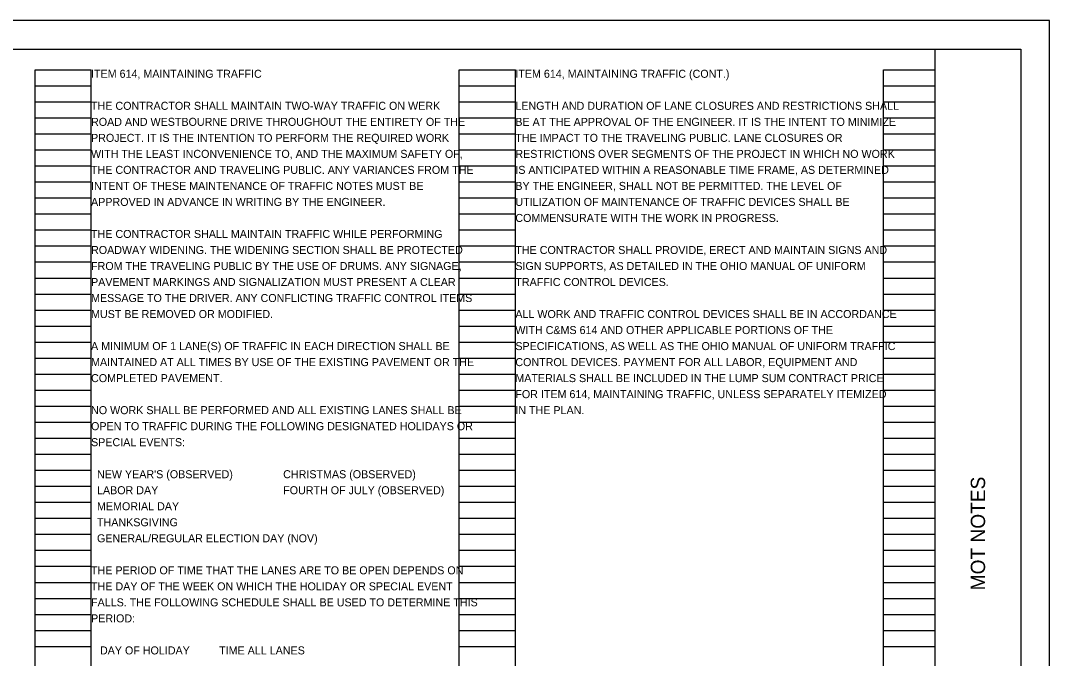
# Model space of a CAD drawing. Extents: x -8.1 to 34, y 0 to 22.
# Drawn here: x 16.01 to 34, y 10.85 to 22 of the extents above; entities that cross this region are included whole.
import ezdxf

# ---------------------------------------------------------------- set-up
doc = ezdxf.new("R2010")
doc.units = 0
for name, color, linetype in [('SH_Border', 7, 'Continuous'), ('SH_Cut_Line', 7, 'Continuous'), ('SH_Data', 7, 'Continuous'), ('SH_Text', 7, 'Continuous')]:
    doc.layers.add(name, color=color, linetype=linetype)

msp = doc.modelspace()

# ---------------------------------------------------------------- linework, layer by layer
at = {"layer": 'SH_Border'}
msp.add_line((32, 0.5), (32, 21.5), dxfattribs=at)
msp.add_lwpolyline([(1.5, 21.5), (33.5, 21.5), (33.5, 0.5), (1.5, 0.5)], close=True, dxfattribs=at)
at = {"layer": 'SH_Cut_Line'}
msp.add_lwpolyline([(0, 0), (34, 0), (34, 22), (0, 22)], close=True, dxfattribs=at)
at = {"layer": 'SH_Data'}
for p, q in [((16.26, 0.98), (16.26, 21.14)), ((16.26, 21.14), (17.24, 21.14)), ((17.24, 0.98), (17.24, 21.14)), ((23.68, 0.98), (23.68, 21.14)), ((23.68, 21.14), (24.66, 21.14)), ((24.66, 0.98), (24.66, 21.14)), ((31.1, 0.98), (31.1, 21.14)), ((31.1, 21.14), (32, 21.14)), ((32, 0.98), (32, 21.14)), ((16.26, 20.86), (17.24, 20.86)), ((23.68, 20.86), (24.66, 20.86)), ((31.1, 20.86), (32, 20.86)), ((16.26, 20.58), (17.24, 20.58)), ((23.68, 20.58), (24.66, 20.58)), ((31.1, 20.58), (32, 20.58)), ((16.26, 20.3), (17.24, 20.3)), ((23.68, 20.3), (24.66, 20.3)), ((31.1, 20.3), (32, 20.3)), ((16.26, 20.02), (17.24, 20.02)), ((23.68, 20.02), (24.66, 20.02)), ((31.1, 20.02), (32, 20.02)), ((16.26, 19.74), (17.24, 19.74)), ((23.68, 19.74), (24.66, 19.74)), ((31.1, 19.74), (32, 19.74)), ((16.26, 19.46), (17.24, 19.46)), ((23.68, 19.46), (24.66, 19.46)), ((31.1, 19.46), (32, 19.46)), ((16.26, 19.18), (17.24, 19.18)), ((23.68, 19.18), (24.66, 19.18)), ((31.1, 19.18), (32, 19.18)), ((16.26, 18.9), (17.24, 18.9)), ((23.68, 18.9), (24.66, 18.9)), ((31.1, 18.9), (32, 18.9)), ((16.26, 18.62), (17.24, 18.62)), ((23.68, 18.62), (24.66, 18.62)), ((31.1, 18.62), (32, 18.62)), ((16.26, 18.34), (17.24, 18.34)), ((23.68, 18.34), (24.66, 18.34)), ((31.1, 18.34), (32, 18.34)), ((16.26, 18.06), (17.24, 18.06)), ((23.68, 18.06), (24.66, 18.06)), ((31.1, 18.06), (32, 18.06)), ((16.26, 17.78), (17.24, 17.78)), ((23.68, 17.78), (24.66, 17.78)), ((31.1, 17.78), (32, 17.78)), ((16.26, 17.5), (17.24, 17.5)), ((23.68, 17.5), (24.66, 17.5)), ((31.1, 17.5), (32, 17.5)), ((16.26, 17.22), (17.24, 17.22)), ((23.68, 17.22), (24.66, 17.22)), ((31.1, 17.22), (32, 17.22)), ((16.26, 16.94), (17.24, 16.94)), ((23.68, 16.94), (24.66, 16.94)), ((31.1, 16.94), (32, 16.94)), ((16.26, 16.66), (17.24, 16.66)), ((23.68, 16.66), (24.66, 16.66)), ((31.1, 16.66), (32, 16.66)), ((16.26, 16.38), (17.24, 16.38)), ((23.68, 16.38), (24.66, 16.38)), ((31.1, 16.38), (32, 16.38)), ((16.26, 16.1), (17.24, 16.1)), ((23.68, 16.1), (24.66, 16.1)), ((31.1, 16.1), (32, 16.1)), ((16.26, 15.82), (17.24, 15.82)), ((23.68, 15.82), (24.66, 15.82)), ((31.1, 15.82), (32, 15.82)), ((16.26, 15.54), (17.24, 15.54)), ((23.68, 15.54), (24.66, 15.54)), ((31.1, 15.54), (32, 15.54)), ((16.26, 15.26), (17.24, 15.26)), ((23.68, 15.26), (24.66, 15.26)), ((31.1, 15.26), (32, 15.26)), ((16.26, 14.98), (17.24, 14.98)), ((23.68, 14.98), (24.66, 14.98)), ((31.1, 14.98), (32, 14.98)), ((16.26, 14.7), (17.24, 14.7)), ((23.68, 14.7), (24.66, 14.7)), ((31.1, 14.7), (32, 14.7)), ((16.26, 14.42), (17.24, 14.42)), ((23.68, 14.42), (24.66, 14.42)), ((31.1, 14.42), (32, 14.42)), ((16.26, 14.14), (17.24, 14.14)), ((23.68, 14.14), (24.66, 14.14)), ((31.1, 14.14), (32, 14.14)), ((16.26, 13.86), (17.24, 13.86)), ((23.68, 13.86), (24.66, 13.86)), ((31.1, 13.86), (32, 13.86)), ((16.26, 13.58), (17.24, 13.58)), ((23.68, 13.58), (24.66, 13.58)), ((31.1, 13.58), (32, 13.58)), ((16.26, 13.3), (17.24, 13.3)), ((23.68, 13.3), (24.66, 13.3)), ((31.1, 13.3), (32, 13.3)), ((16.26, 13.02), (17.24, 13.02)), ((23.68, 13.02), (24.66, 13.02)), ((31.1, 13.02), (32, 13.02)), ((16.26, 12.74), (17.24, 12.74)), ((23.68, 12.74), (24.66, 12.74)), ((31.1, 12.74), (32, 12.74)), ((16.26, 12.46), (17.24, 12.46)), ((23.68, 12.46), (24.66, 12.46)), ((31.1, 12.46), (32, 12.46)), ((16.26, 12.18), (17.24, 12.18)), ((23.68, 12.18), (24.66, 12.18)), ((31.1, 12.18), (32, 12.18)), ((16.26, 11.9), (17.24, 11.9)), ((23.68, 11.9), (24.66, 11.9)), ((31.1, 11.9), (32, 11.9)), ((16.26, 11.62), (17.24, 11.62)), ((23.68, 11.62), (24.66, 11.62)), ((31.1, 11.62), (32, 11.62)), ((16.26, 11.34), (17.24, 11.34)), ((23.68, 11.34), (24.66, 11.34)), ((31.1, 11.34), (32, 11.34)), ((16.26, 11.06), (17.24, 11.06)), ((23.68, 11.06), (24.66, 11.06)), ((31.1, 11.06), (32, 11.06))]:
    msp.add_line(p, q, dxfattribs=at)

# ---------------------------------------------------------------- texts
msp.add_text('MOT NOTES', height=0.25, rotation=90, dxfattribs=at).set_placement((32.875, 12.04))
at = {"layer": 'SH_Text'}
for s, p in [('ITEM 614, MAINTAINING TRAFFIC', (17.24, 21)), ('ITEM 614, MAINTAINING TRAFFIC (CONT.)', (24.66, 21)), ('THE CONTRACTOR SHALL MAINTAIN TWO-WAY TRAFFIC ON WERK ', (17.24, 20.44)), ('LENGTH AND DURATION OF LANE CLOSURES AND RESTRICTIONS SHALL ', (24.66, 20.44)), ('ROAD AND WESTBOURNE DRIVE THROUGHOUT THE ENTIRETY OF THE ', (17.24, 20.16)), ('BE AT THE APPROVAL OF THE ENGINEER. IT IS THE INTENT TO MINIMIZE ', (24.66, 20.16)), ('PROJECT. IT IS THE INTENTION TO PERFORM THE REQUIRED WORK ', (17.24, 19.88)), ('THE IMPACT TO THE TRAVELING PUBLIC. LANE CLOSURES OR ', (24.66, 19.88)), ('WITH THE LEAST INCONVENIENCE TO, AND THE MAXIMUM SAFETY OF, ', (17.24, 19.6)), ('RESTRICTIONS OVER SEGMENTS OF THE PROJECT IN WHICH NO WORK ', (24.66, 19.6)), ('THE CONTRACTOR AND TRAVELING PUBLIC. ANY VARIANCES FROM THE ', (17.24, 19.32)), ('IS ANTICIPATED WITHIN A REASONABLE TIME FRAME, AS DETERMINED ', (24.66, 19.32)), ('INTENT OF THESE MAINTENANCE OF TRAFFIC NOTES MUST BE ', (17.24, 19.04)), ('BY THE ENGINEER, SHALL NOT BE PERMITTED. THE LEVEL OF ', (24.66, 19.04)), ('APPROVED IN ADVANCE IN WRITING BY THE ENGINEER. ', (17.24, 18.76)), ('UTILIZATION OF MAINTENANCE OF TRAFFIC DEVICES SHALL BE ', (24.66, 18.76)), ('COMMENSURATE WITH THE WORK IN PROGRESS.', (24.66, 18.48)), ('THE CONTRACTOR SHALL MAINTAIN TRAFFIC WHILE PERFORMING ', (17.24, 18.2)), ('ROADWAY WIDENING. THE WIDENING SECTION SHALL BE PROTECTED ', (17.24, 17.92)), ('THE CONTRACTOR SHALL PROVIDE, ERECT AND MAINTAIN SIGNS AND ', (24.66, 17.92)), ('FROM THE TRAVELING PUBLIC BY THE USE OF DRUMS. ANY SIGNAGE, ', (17.24, 17.64)), ('SIGN SUPPORTS, AS DETAILED IN THE OHIO MANUAL OF UNIFORM ', (24.66, 17.64)), ('PAVEMENT MARKINGS AND SIGNALIZATION MUST PRESENT A CLEAR ', (17.24, 17.36)), ('TRAFFIC CONTROL DEVICES.', (24.66, 17.36)), ('MESSAGE TO THE DRIVER. ANY CONFLICTING TRAFFIC CONTROL ITEMS ', (17.24, 17.08)), ('MUST BE REMOVED OR MODIFIED.', (17.24, 16.8)), ('ALL WORK AND TRAFFIC CONTROL DEVICES SHALL BE IN ACCORDANCE ', (24.66, 16.8)), ('WITH C&MS 614 AND OTHER APPLICABLE PORTIONS OF THE ', (24.66, 16.52)), ('A MINIMUM OF 1 LANE(S) OF TRAFFIC IN EACH DIRECTION SHALL BE ', (17.24, 16.24)), ('SPECIFICATIONS, AS WELL AS THE OHIO MANUAL OF UNIFORM TRAFFIC ', (24.66, 16.24)), ('MAINTAINED AT ALL TIMES BY USE OF THE EXISTING PAVEMENT OR THE ', (17.24, 15.96)), ('CONTROL DEVICES. PAYMENT FOR ALL LABOR, EQUIPMENT AND ', (24.66, 15.96)), ('COMPLETED PAVEMENT.', (17.24, 15.68)), ('MATERIALS SHALL BE INCLUDED IN THE LUMP SUM CONTRACT PRICE ', (24.66, 15.68)), ('FOR ITEM 614, MAINTAINING TRAFFIC, UNLESS SEPARATELY ITEMIZED ', (24.66, 15.4)), ('NO WORK SHALL BE PERFORMED AND ALL EXISTING LANES SHALL BE ', (17.24, 15.12)), ('IN THE PLAN.', (24.66, 15.12)), ('OPEN TO TRAFFIC DURING THE FOLLOWING DESIGNATED HOLIDAYS OR ', (17.24, 14.84)), ('SPECIAL EVENTS:', (17.24, 14.56)), ("  NEW YEAR'S (OBSERVED)", (17.24, 14)), ('CHRISTMAS (OBSERVED)', (20.6, 14)), ('  LABOR DAY', (17.24, 13.72)), ('FOURTH OF JULY (OBSERVED)', (20.6, 13.72)), ('  MEMORIAL DAY', (17.24, 13.44)), ('  THANKSGIVING', (17.24, 13.16)), ('  GENERAL/REGULAR ELECTION DAY (NOV)', (17.24, 12.88)), ('THE PERIOD OF TIME THAT THE LANES ARE TO BE OPEN DEPENDS ON ', (17.24, 12.32)), ('THE DAY OF THE WEEK ON WHICH THE HOLIDAY OR SPECIAL EVENT ', (17.24, 12.04)), ('FALLS. THE FOLLOWING SCHEDULE SHALL BE USED TO DETERMINE THIS ', (17.24, 11.76)), ('PERIOD:', (17.24, 11.48)), ('   DAY OF HOLIDAY     ', (17.24, 10.92)), ('TIME ALL LANES', (19.48, 10.92))]:
    msp.add_text(s, height=0.14, dxfattribs=at).set_placement(p)

doc.saveas('drawing.dxf')
